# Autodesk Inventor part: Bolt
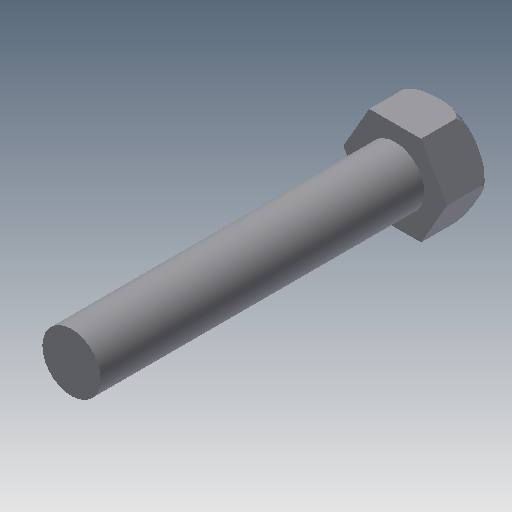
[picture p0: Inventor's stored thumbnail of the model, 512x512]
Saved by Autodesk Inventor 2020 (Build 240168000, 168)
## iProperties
Created: 2002-02
Part Number: Bolt
Document SubType Name: Modeling
Designer: ***
Density: 1 g/cm^3
Material: Generic
Appearance: Default
Control State: 0
Master: False
Checked Out: False
Shininess: 77.0
Length Units: 11269
Angle Units: 11279
Time Units: 11290
Mass Units: 11283
Length Display Precision: 3
Angle Display Precision: 2
Density: 0.0
Volumn: 0.0
Area: 0.0
PropertySet Name: Model Information
Author: ***
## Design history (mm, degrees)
sketch "Sketch1"
  geometry: C1 r 4 at (0, 0)
  constraints: 1 centre point
  dimensions: "d0" = 8 diameter of C1
extrude "Extrusion1" new body sketch "Sketch1" stored distance "d1" = 3.5; taper "d2" = 0 deg
fillet "Fillet1" dims "d3" = 1
sketch "Sketch2"
  geometry: L1 (4, 0)-(2, -3.464); L2 (2, -3.464)-(-2, -3.464); L3 (-2, -3.464)-(-4, 0); L4 (-4, 0)-(-2, 3.464); L5 (-2, 3.464)-(2, 3.464); L6 (2, 3.464)-(4, 0); 2 further points
  constraints: 12 end point, 1 coincident, 11 other
extrude "Extrusion2" sketch "Sketch2" extent not by distance; stored distance "d4" = 3.5; taper "d5" = 0 deg
sketch "Sketch3"
  geometry: C1 r 2.25 at (0, 0)
  constraints: 1 centre point
  dimensions: "d6" = 4.5 diameter of C1
extrude "Extrusion3" join sketch "Sketch3" distance "d7" = 25; taper "d8" = 0 deg
body "Solid1"
